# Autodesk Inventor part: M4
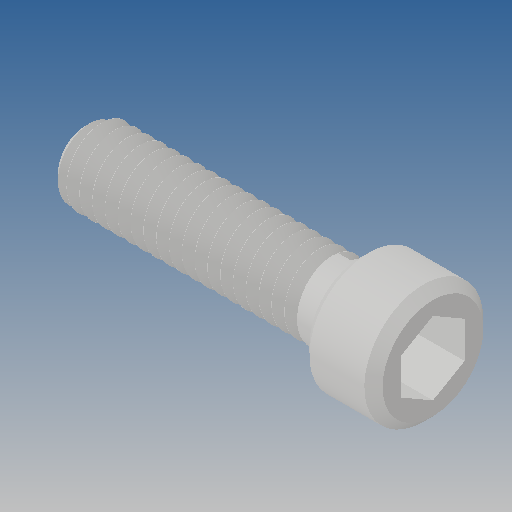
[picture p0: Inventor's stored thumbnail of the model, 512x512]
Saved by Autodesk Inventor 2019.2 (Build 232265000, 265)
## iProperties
Created: 2009-09
Part Number: M4
Material: Ogólny
Document SubType Name: Modeling
Designer: CADENGINEERING4
Density: 1 g/cm^3
Appearance: Domyślna
Author: CADENGINEERING4
Revision Number: 1LAST_VERSION
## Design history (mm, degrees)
feature "Baza1"
node "Bryła1"
